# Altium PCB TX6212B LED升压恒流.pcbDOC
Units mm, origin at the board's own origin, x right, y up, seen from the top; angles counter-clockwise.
Board outline 48.79 x 35.61 mm, 2 copper layers (TopLayer, BottomLayer); 34 components, 15 nets, 80 pads, 107 vias.
Unrouted connection lines stored in the file: 1.
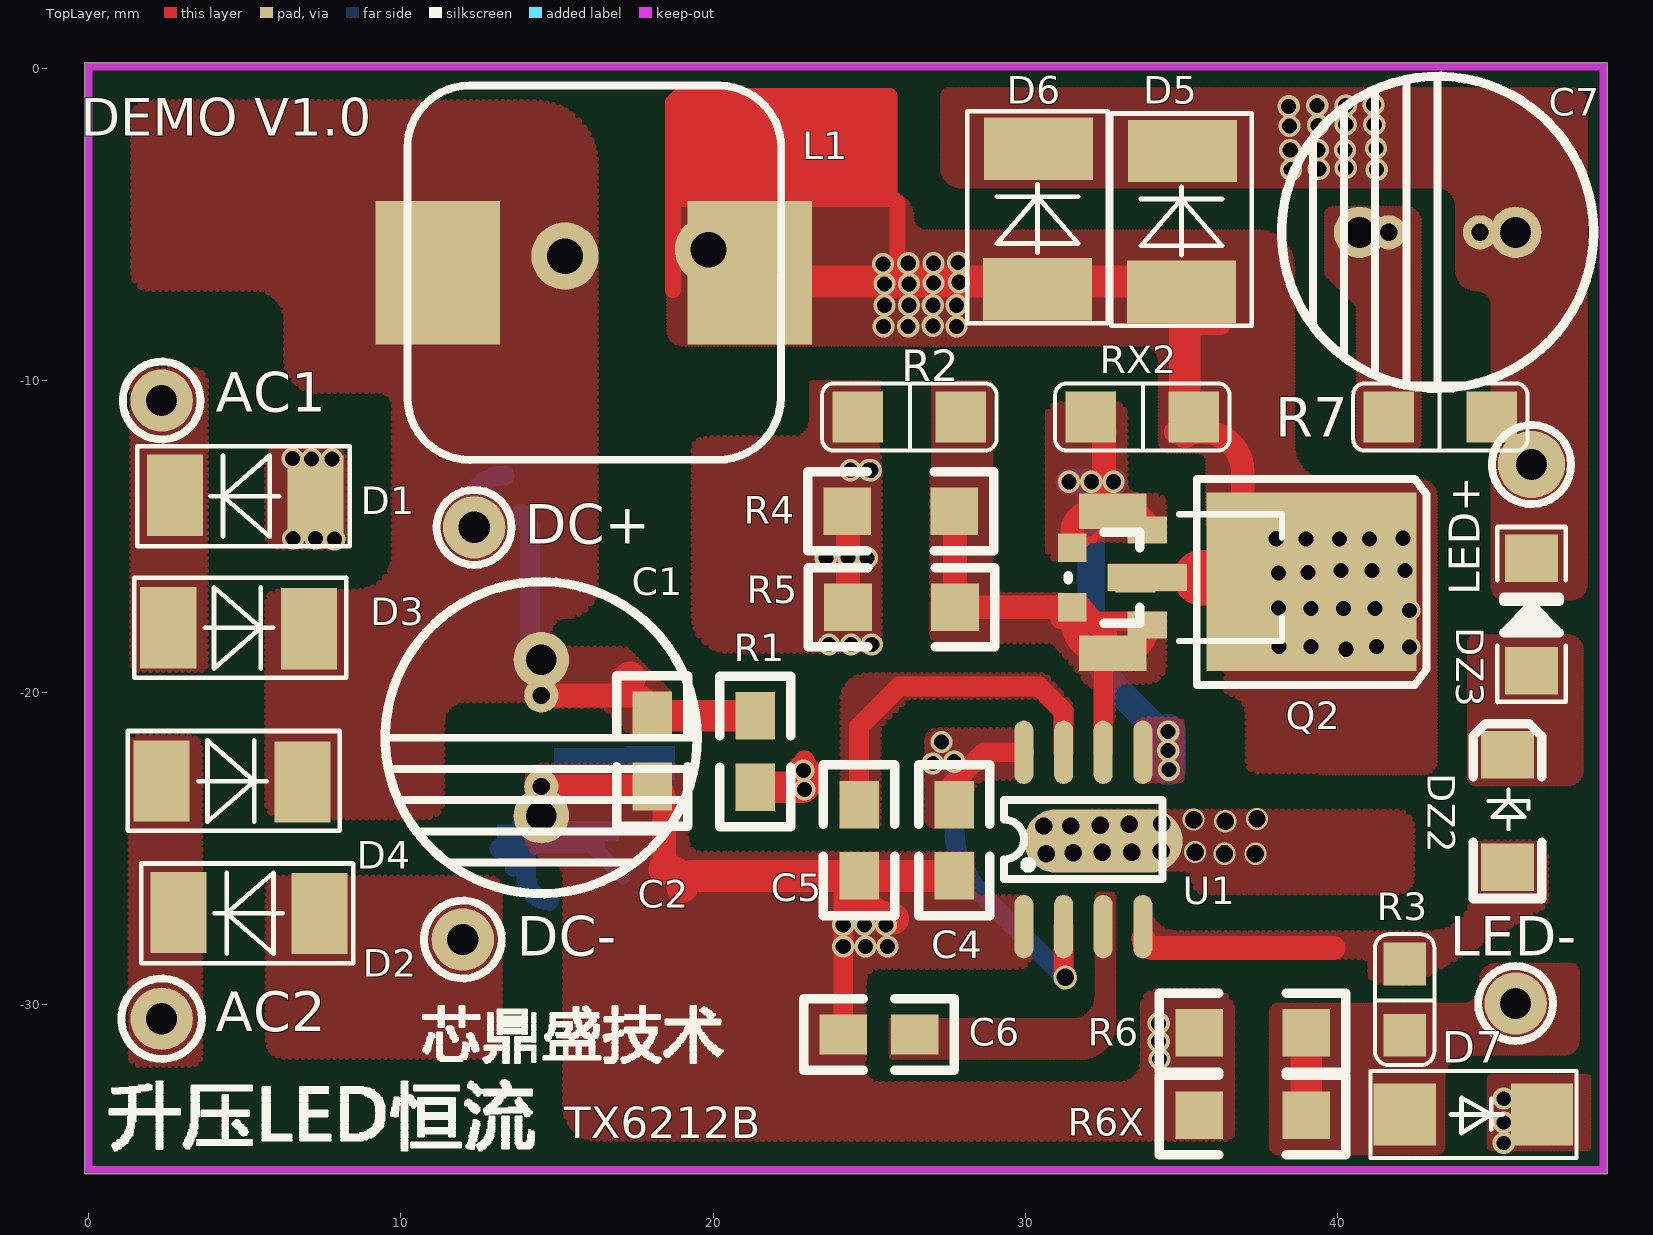
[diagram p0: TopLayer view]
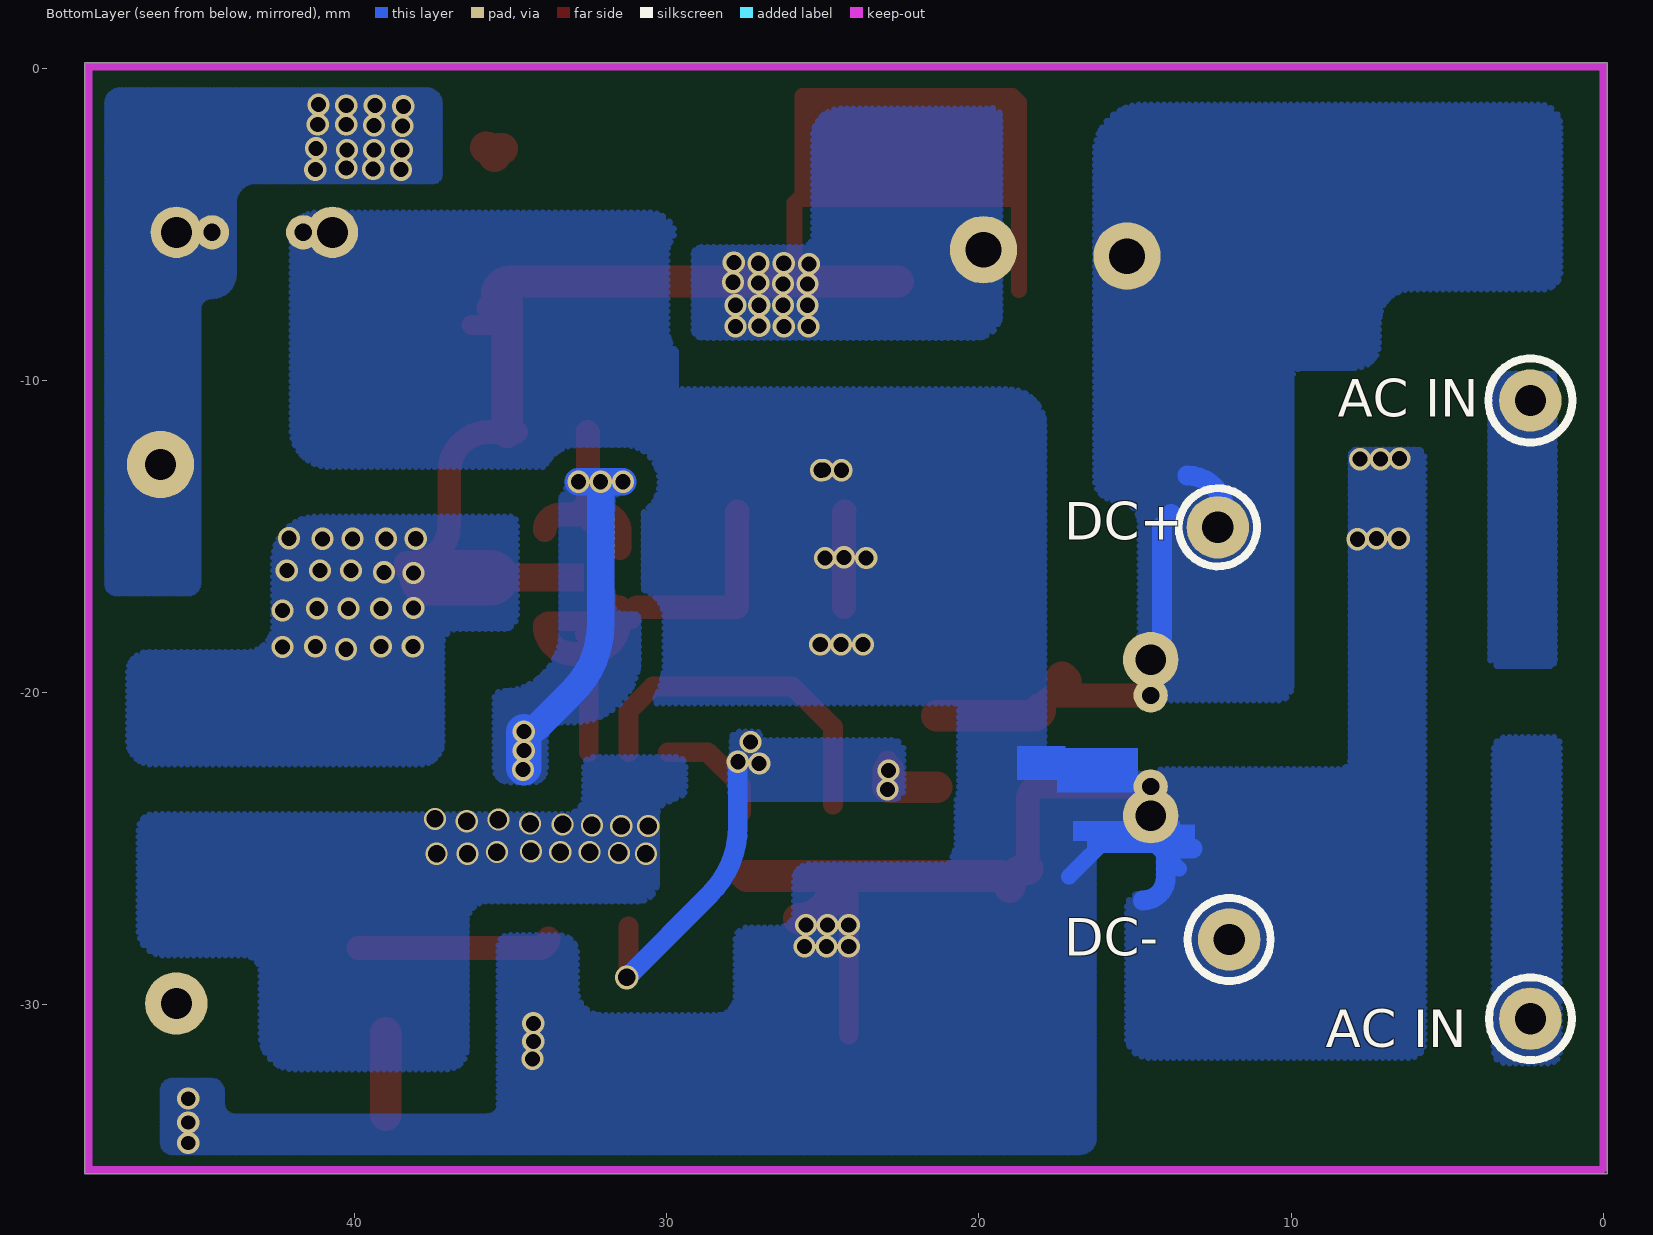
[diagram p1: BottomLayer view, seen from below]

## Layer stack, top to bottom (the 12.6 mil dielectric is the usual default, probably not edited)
TopLayer: signal copper 0.0356
Dielectric: dielectric 0.32, FR-4, Dk 4.8
BottomLayer: signal copper 0.0356

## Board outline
-0.135,-35.433 48.658,-35.433 48.658,0.178 -0.135,0.178

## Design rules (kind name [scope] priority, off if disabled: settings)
Clearance [All] p0: scope1count=1 scope1_0_kind=Board scope1_0_value=Board scope2count=1 scope2_0_kind=Board scope2_0_value=Board commentlength=0 gap=0.254
Clearance [All] p1: gap=0.254
ComponentClearance [All] p0 off: scope1count=1 scope1_0_kind=Board scope1_0_value=Board scope2count=1 scope2_0_kind=Board scope2_0_value=Board commentlength=0 gap=0.254 collisioncheckmode=3
ComponentClearance [All] p1 off: gap=0.254 collisioncheckmode=3 verticalgap=0.254 showdistances=FALSE
DiffPairsRouting [All] p0: scope1count=1 scope1_0_kind=Board scope1_0_value=Board scope2count=1 scope2_0_kind=Board scope2_0_value=Board commentlength=0
FanoutControl Fanout_BGA [All] p0 off: scope1count=1 scope1_0_kind=Board scope1_0_value=Board scope2count=1 scope2_0_kind=Board scope2_0_value=Board commentlength=69 // Protel DXP Scope 1 Expression Was: IsBGA   Fanout_BGA (Default Rule)
FanoutControl Fanout_LCC [All] p0 off: scope1count=1 scope1_0_kind=Board scope1_0_value=Board scope2count=1 scope2_0_kind=Board scope2_0_value=Board commentlength=69 // Protel DXP Scope 1 Expression Was: IsLCC   Fanout_LCC (Default Rule)
FanoutControl Fanout_SOIC [All] p0 off: scope1count=1 scope1_0_kind=Board scope1_0_value=Board scope2count=1 scope2_0_kind=Board scope2_0_value=Board commentlength=71 // Protel DXP Scope 1 Expression Was: IsSOIC   Fanout_SOIC (Default Rule)
FanoutControl Fanout_Small [All] p0 off: scope1count=1 scope1_0_kind=Board scope1_0_value=Board scope2count=1 scope2_0_kind=Board scope2_0_value=Board commentlength=84 // Protel DXP Scope 1 Expression Was: (CompPinCount < 5)   Fanout_Small (Default Rule)
FanoutControl Fanout_Default [All] p0: scope1count=1 scope1_0_kind=Board scope1_0_value=Board scope2count=1 scope2_0_kind=Board scope2_0_value=Board commentlength=30 // Fanout_Default (Default Rule)
FanoutControl Fanout_LCC [All] p1 off: bgadir=Out bgaviamode=Centered fanoutstyle=Auto fanoutdirection=Alternating viagrid=0.025 // Protel DXP Scope 1 Expression Was: IsLCC   Fanout_LCC (Default Rule)
FanoutControl Fanout_BGA [All] p2 off: bgadir=Out bgaviamode=Centered fanoutstyle=Auto fanoutdirection=Alternating viagrid=0.025 // Protel DXP Scope 1 Expression Was: IsBGA   Fanout_BGA (Default Rule)
FanoutControl Fanout_SOIC [All] p3 off: bgadir=Out bgaviamode=Centered fanoutstyle=Auto fanoutdirection=Alternating viagrid=0.025 // Protel DXP Scope 1 Expression Was: IsSOIC   Fanout_SOIC (Default Rule)
FanoutControl Fanout_Default [All] p4: bgadir=Out bgaviamode=Centered fanoutstyle=Auto fanoutdirection=Alternating viagrid=0.025 // Fanout_Default (Default Rule)
FanoutControl Fanout_Small [All] p5 off: bgadir=Out bgaviamode=Centered fanoutstyle=Auto fanoutdirection=Alternating viagrid=0.025 // Protel DXP Scope 1 Expression Was: (CompPinCount < 5)   Fanout_Small (Default Rule)
Height [All] p0: scope1count=1 scope1_0_kind=Board scope1_0_value=Board scope2count=1 scope2_0_kind=Board scope2_0_value=Board commentlength=0
HoleSize [All] p0: scope1count=1 scope1_0_kind=Board scope1_0_value=Board scope2count=1 scope2_0_kind=Board scope2_0_value=Board commentlength=0 absolutevalues=TRUE maxlimit=2.54 minlimit=0.025 maxpercent=80.000 minpercent=20.000
HoleToHoleClearance [All] p0: scope1count=1 scope1_0_kind=Board scope1_0_value=Board scope2count=1 scope2_0_kind=Board scope2_0_value=Board commentlength=0
LayerPairs [All] p0: scope1count=1 scope1_0_kind=Board scope1_0_value=Board scope2count=1 scope2_0_kind=Board scope2_0_value=Board commentlength=0 enforce=TRUE
MinimumSolderMaskSliver [All] p0: scope1count=1 scope1_0_kind=Board scope1_0_value=Board scope2count=1 scope2_0_kind=Board scope2_0_value=Board commentlength=0
NetAntennae [All] p0: scope1count=1 scope1_0_kind=Board scope1_0_value=Board scope2count=1 scope2_0_kind=Board scope2_0_value=Board commentlength=0
PasteMaskExpansion [All] p0: scope1count=1 scope1_0_kind=Board scope1_0_value=Board scope2count=1 scope2_0_kind=Board scope2_0_value=Board commentlength=0 expansion=0
PlaneClearance [All] p0: scope1count=1 scope1_0_kind=Board scope1_0_value=Board scope2count=1 scope2_0_kind=Board scope2_0_value=Board commentlength=0 clearance=0.508
PlaneConnect [All] p0: scope1count=1 scope1_0_kind=Board scope1_0_value=Board scope2count=1 scope2_0_kind=Board scope2_0_value=Board commentlength=0 planeconnectstyle=Relief reliefexpansion=0.508 reliefentries=4 reliefconductorwidth=0.254 reliefairgap=0.254
PolygonConnect [All] p0: scope1count=1 scope1_0_kind=Board scope1_0_value=Board scope2count=1 scope2_0_kind=Board scope2_0_value=Board commentlength=0 connectstyle=Direct reliefconductorwidth=0.254 reliefentries=4 polygonreliefangle="90 Angle"
PolygonConnect [All] p1: connectstyle=Direct reliefconductorwidth=0.254 reliefentries=4 polygonreliefangle="90 Angle"
RoutingCorners [All] p0: scope1count=1 scope1_0_kind=Board scope1_0_value=Board scope2count=1 scope2_0_kind=Board scope2_0_value=Board commentlength=0 cornerstyle=45-Degree minsetback=2.54 maxsetback=2.54
RoutingLayers [All] p0: scope1count=1 scope1_0_kind=Board scope1_0_value=Board scope2count=1 scope2_0_kind=Board scope2_0_value=Board commentlength=0 top layer=Horizontal bottom layer=Vertical
RoutingPriority [All] p0: scope1count=1 scope1_0_kind=Board scope1_0_value=Board scope2count=1 scope2_0_kind=Board scope2_0_value=Board commentlength=0
RoutingTopology [All] p0: scope1count=1 scope1_0_kind=Board scope1_0_value=Board scope2count=1 scope2_0_kind=Board scope2_0_value=Board commentlength=0 topology=Shortest
RoutingVias [All] p0: scope1count=1 scope1_0_kind=Board scope1_0_value=Board scope2count=1 scope2_0_kind=Board scope2_0_value=Board commentlength=0 holewidth=0.711 width=1.27 viastyle="Through Hole" minholewidth=0.711 minwidth=1.27 maxholewidth=0.711 maxwidth=1.27
RoutingVias [All] p1: holewidth=0.711 width=1.27 viastyle="Through Hole" minholewidth=0.711 minwidth=1.27 maxholewidth=0.711 maxwidth=1.27
ShortCircuit [All] p0: scope1count=1 scope1_0_kind=Board scope1_0_value=Board scope2count=1 scope2_0_kind=Board scope2_0_value=Board commentlength=0 allowed=FALSE
SilkToSilkClearance [All] p0: scope1count=1 scope1_0_kind=Board scope1_0_value=Board scope2count=1 scope2_0_kind=Board scope2_0_value=Board commentlength=0
SilkscreenOverComponentPads [All] p0: scope1count=1 scope1_0_kind=Board scope1_0_value=Board scope2count=1 scope2_0_kind=Board scope2_0_value=Board commentlength=0
SilkscreenOverComponentPads [All] p1: minsilkscreentomaskgap=0.254
SolderMaskExpansion [All] p0: scope1count=1 scope1_0_kind=Board scope1_0_value=Board scope2count=1 scope2_0_kind=Board scope2_0_value=Board commentlength=0 expansion=0.102
SolderMaskExpansion [All] p1: expansion=0.102
TestPointUsage [All] p0: scope1count=1 scope1_0_kind=Board scope1_0_value=Board scope2count=1 scope2_0_kind=Board scope2_0_value=Board commentlength=0 valid=0 allowmultiple=FALSE
TestPointUsage [All] p1: valid=0 allowmultiple=FALSE
Testpoint [All] p0: scope1count=1 scope1_0_kind=Board scope1_0_value=Board scope2count=1 scope2_0_kind=Board scope2_0_value=Board commentlength=0 side=15 testpointundercomponent=TRUE minsize=1.016 maxsize=2.54 preferedsize=1.524 minholesize=0.508 maxholesize=1.016 preferedholesize=0.813 testpointgrid=0.025 style=1023 order=0123456789
Testpoint [All] p1: side=15 testpointundercomponent=TRUE minsize=1.016 maxsize=2.54 preferedsize=1.524 minholesize=0.508 maxholesize=1.016 preferedholesize=0.813 testpointgrid=0.025 style=1023 order=0123456789
UnRoutedNet [All] p0: scope1count=1 scope1_0_kind=Board scope1_0_value=Board scope2count=1 scope2_0_kind=Board scope2_0_value=Board commentlength=0
Width [All] p0: scope1count=1 scope1_0_kind=Board scope1_0_value=Board scope2count=1 scope2_0_kind=Board scope2_0_value=Board commentlength=0 maxlimit=0.254 minlimit=0.254 preferedwidth=0.254
Width [All] p1: maxlimit=0.254 minlimit=0.254 preferedwidth=0.254
17 further rules are at their usual default settings.

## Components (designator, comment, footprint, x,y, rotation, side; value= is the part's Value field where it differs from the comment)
C1 "" CINJ#1 14.497,-18.954 r0 top
C2 "" 0805 18.053,-23.018 r90 top
C4 "" 0805 27.728,-25.883 r90 top
C5 "" 0805 24.68,-25.883 r90 top
C6 "" 0805 24.172,-30.963 r0 top
C7 "" CINJ#2 45.72,-5.258 r270 top
D1 "" SMB 7.265,-13.716 r180 top
D2 "" SMB 7.384,-27.082 r180 top
D3 "" SMB 2.54,-17.93 r0 top
D4 "" SMB 2.33,-22.84 r0 top
D5 "" SMBJ 35.011,-7.163 r90 top
D6 "" SMBJ 30.395,-7.087 r90 top
D7 "" SMA 42.164,-33.528 r180 top
DZ2 "" DZJ 146.456,79.891 r0 top
DZ3 "" DZSMA 46.228,-19.304 r0 top
L1 "" TJJ 11.176,-6.551 r0 top
Q2 "" QJJ 32.808,-14.199 r0 top
R1 "" 0805 21.353,-20.752 r270 top
R2 "" R1206 27.94,-11.176 r270 top
R3 "" R0805 42.164,-30.988 r0 top
R4 "" 1206 27.728,-14.199 r180 top
R5 "" 1206 24.325,-17.272 r0 top
R6 "" 1206 35.577,-30.912 r0 top
R6X "" 1206 35.577,-33.546 r0 top
R7 "" R1206 41.656,-11.176 r90 top
RX2 "" R1206 35.407,-11.176 r270 top
U1 "" SO8J 29.964,-27.508 r90 top
? "" DIP 15.257,-6.02 r0 top
? "LED-" OUT#1 45.72,-29.972 r0 top
? "LED+" OUT#2 46.228,-12.7 r0 top
? "DC+" OUT#1 12.345,-14.712 r0 top
? "DC-" OUT#1 11.982,-27.92 r0 top
? "AC2" OUT#1 2.33,-30.46 r0 top
? "AC1" OUT#1 2.33,-10.648 r0 top

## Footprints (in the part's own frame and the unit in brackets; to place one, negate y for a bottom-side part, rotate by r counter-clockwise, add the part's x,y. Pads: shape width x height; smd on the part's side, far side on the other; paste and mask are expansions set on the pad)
0805 [mil]
  rect 60x50 smd: 1(0,0) 2(90,0)
  silkscreen extent -50,-45 140,45
1206 [mil]
  rect 60x60 smd: 1(0,0) 2(135,0)
  silkscreen extent -50,-50 185,50
CINJ#1 [mil]
  round 70 hole 39: 1(0,0) 2(0,-196.85)
  round 43.31 hole 21.65: 1(0,-45) 2(0,-160)
  silkscreen extent -197,-295 197,98
CINJ#2 [mil]
  round 65 hole 39: 1(0,0) 2(0,-196.85)
  round 43.31 hole 21.65: 1(0,-45) 2(0,-160)
  silkscreen extent -197,-295 197,98
DIP [mil]
  round 85 hole 45: 1(0,0) 2(181,8)
DZJ [mm]
  rect 1.7x1.524 smd: 1(-100.999,-105.497) 2(-100.999,-101.897)
  silkscreen extent -102.1,-106.5 -99.9,-100.9
DZSMA [mm]
  rect 1.7x1.524 smd: 1(0,0) 2(0,3.6)
  silkscreen extent -1.1,-1.01 1.1,4.6
OUT#1 [mm]
  round 2 hole 1: 1(0,0)
OUT#2 [mm]
  round 2.159 hole 1: 1(0,0)
QJJ [mil]
  rect 36x36 smd: 1(-51.18,-46.26) 3(-51.18,-121.26)
  rect 85x45 smd: 1(0,0) 3(0,-179)
  rect 50x34 smd: 1(43.62,-23.66) 3(43.62,-143.66)
  rect 50x36 smd: 2(28.82,-84.26)
  rect 100x34 smd: 2(43.62,-83.66)
  rect 265x225 smd: 2(251,-89)
  TopLayer region: -5.91,-101.38 183.07,-101.38 183.07,-65.94 -5.91,-65.94
  TopLayer lines w10: -51.18,-46.26 -40.74,-46.26 ; -45.27,-109.25 -41.34,-109.25 ; 18.9,-185.24 28.34,-185.24
  TopLayer lines w70: 112,-83.66 192,-83.66
  silkscreen extent -56,-219 396,41
R0805 [mil]
  rect 54x54 smd: 1(0,0) 2(0,90)
  silkscreen extent -38,-38 38,128
R1206 [mil]
  rect 64x64 smd: 1(0,0) 2(0,-130)
  silkscreen extent -43,-175 43,45
SMA [mm]
  rect 2x2 smd: 1(0,0) 2(-4.4,0)
  silkscreen extent -5.5,-1.4 1.1,1.4
SMB [mm]
  rect 1.8x2.6 smd: 1(0,0) 2(4.511,-0.031)
  silkscreen extent -1.09,-1.6 5.71,1.6
SMBJ [mm]
  rect 2x3.5 smd: 1(0,0) 2(4.511,-0.031)
  silkscreen extent -1.09,-2.25 5.71,2.25
SO8J [mil]
  oval 80x200 smd: 0(108,-100.33)
  oval 80x24 smd: 1(0,0) 2(0,-50) 3(0,-100) 4(0,-150) 5(220,-150) 6(220,-100) 7(220,-50) 8(220,0)
  silkscreen extent 60,-175 160,25
TJJ [mm]
  rect 4x4.6 smd: 1(0,0) 2(10,0)
  silkscreen extent -0.97,-6 11.01,6

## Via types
v1: diameter 0.711, hole 0.483, TopLayer to BottomLayer, 87 vias
v2: diameter 0.711, hole 0.559, TopLayer to BottomLayer, 16 vias
v3: diameter 0.711, hole 0.457, TopLayer to BottomLayer, 3 vias
v4: diameter 0.762, hole 0.559, TopLayer to BottomLayer, 1 vias

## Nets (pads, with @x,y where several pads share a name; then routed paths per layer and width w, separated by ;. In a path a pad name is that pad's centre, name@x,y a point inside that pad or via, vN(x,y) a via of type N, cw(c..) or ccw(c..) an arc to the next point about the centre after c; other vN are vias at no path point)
GND: ?.1@11.982,-27.92 C1.2 C2.1 C4.1 C5.1 C6.1 C7.2 D1.1 D2.1 D7.2 R2.2 R4.2 R5.1 R6.1 R6X.1 R7.1 U1.1 | length 32
  TopLayer w0.635: C6.1 24.172,-26.441 C5.1@24.528,-26.086 ; C5.1 C4.1
  TopLayer w0.762: C1.2@14.497,-23.018 C2.1 cw(c18.053,-23.399) 18.434,-23.399 18.434,-25.66 ; R4.2 cw(c24.299,-14.224) 24.325,-14.224 R5.1
  TopLayer w1.016: 18.434,-25.66 cw(c18.434,-26.242) 19.016,-26.242 cw(c19.376,-26.242) 19.376,-25.883 C4.1@27.424,-25.883 ; C5.1 24.68,-26.162 ccw(c25.773,-26.162) v1@25.773,-27.254
  BottomLayer w0.635: 13.158,-24.999 13.854,-24.999 cw(c13.854,-25.159) 14.014,-25.159 14.014,-25.931 ccw(c14.751,-25.931) 14.751,-26.668
  other v1: 34.307,-31.75 34.282,-31.191 34.282,-30.607 24.172,-28.143 24.884,-28.143 25.595,-28.143 24.172,-27.457 24.858,-27.457 25.544,-27.457 23.715,-18.466 24.426,-18.466 25.087,-18.466 23.614,-15.697 24.934,-15.697 24.325,-15.672 7.867,-15.093 6.546,-15.068 7.258,-15.068 24.402,-12.883 24.985,-12.878 25.063,-12.883 7.131,-12.528 7.791,-12.528 6.521,-12.502
  other v3: 45.339,-34.442 45.339,-33.782 45.339,-33.02
NetA_1: ?.1@2.33,-10.648 D1.2 D3.1
NetC5_2: C5.2 U1.7 | length 11.2
  TopLayer w0.635: C5.2 24.68,-21.107 25.976,-19.812 30.446,-19.812 31.234,-20.599 U1.7
NetC6_2: C6.2 U1.3
NetD2_2: ?.1@2.33,-30.46 D2.2 D4.1
NetD3_2: ?.1@12.345,-14.712 ?.1@15.257,-6.02 C1.1 C2.2 D3.2 D4.2 L1.1 R1.1 | length 13.6
  TopLayer w0.762: C1.1@14.497,-20.097 17.418,-20.097 cw(c17.418,-20.732) C2.2
  TopLayer w1.016: 17.222,-19.634 ccw(c17.222,-19.516) 17.34,-19.516 ; C2.2@18.035,-20.523 ccw(c18.263,-20.523) 18.263,-20.752 R1.1
  BottomLayer w0.635: ?.1@12.107,-14.273 cw(c13.327,-14.273) 13.327,-13.054 ; 13.844,-14.351 13.844,-14.275 ; C1.1@14.139,-18.692 14.139,-14.679
NetD5_2: ?.1@46.228,-12.7 C7.1 D5.2 D6.2 DZ2.2 DZ3.1 DZ3.2 R7.2 | length 0.8
  TopLayer w1.016: D5.2@35.282,-2.576 cw(c35.282,-2.819) 35.526,-2.819 cw(c35.806,-2.819) D5.2@35.806,-2.54
  other v1: 38.523,-3.251 41.267,-3.251 39.412,-3.226 40.276,-3.2 38.498,-2.616 39.387,-2.616 40.251,-2.616 41.241,-2.565 38.473,-1.854 39.387,-1.829 40.276,-1.803 41.19,-1.803 38.447,-1.219 39.362,-1.194 40.276,-1.194 41.165,-1.168
NetR3_1: ?.1@45.72,-29.972 D7.1 R3.1 R6.2 R6X.2 | length 2.6
  TopLayer w1.016: R6X.2 R6.2
NetRX1_1: C4.2 R1.2 U1.2 U1.8 | length 16.6
  TopLayer w0.635: v1(22.928,-23.114) v1@22.928,-22.174 ; C4.2@27.627,-23.851 27.627,-22.987 28.694,-21.92 U1.8 ; U1.2 31.234,-29.011 ccw(c31.407,-29.011) v4(31.284,-29.134)
  TopLayer w1.016: R1.2 22.852,-23.038 ccw(c22.852,-22.962) 22.928,-22.962 cw(c22.928,-22.936) 22.902,-22.936 v1(22.902,-22.504)
  BottomLayer w0.635: v1(27.728,-22.225) 27.728,-24.308 ccw(c30.794,-24.308) 28.626,-26.476 v4(31.284,-29.134)
  other v1: 27.043,-22.276 27.322,-21.59
NetRX2_1: ?.2 D5.1 D6.1 L1.2 Q2.2 RX2.1 | length 30.8
  TopLayer w0.635: 35.069,-8.23 36.263,-8.23 ; D5.1@35.552,-7.468 cw(c35.552,-7.696) D5.1@35.78,-7.696
  TopLayer w0.762: Q2.2@33.916,-16.324 37.897,-16.324 ccw(c37.897,-15.85) 38.371,-15.85 38.193,-15.85 cw(c38.193,-14.63) 36.974,-14.63 36.974,-12.929 ccw(c35.704,-12.929) 35.704,-11.659 34.84,-11.659 ccw(c34.84,-11.557) RX2.1@34.942,-11.557
  TopLayer w1.016: L1.2@22.598,-6.833 35.044,-6.833 cw(c35.044,-7.239) 35.45,-7.239 ccw(c35.45,-7.569) 35.12,-7.569 RX2.1@35.12,-11.659
  other v1: 40.284,-18.618 38.142,-18.534 39.158,-18.534 41.267,-18.534 42.316,-18.542 42.316,-17.374 39.158,-17.315 40.2,-17.315 41.216,-17.315 38.117,-17.297 38.117,-16.18 39.064,-16.154 40.124,-16.096 41.114,-16.096 42.181,-16.096 38.048,-15.079 39.006,-15.08 40.073,-15.08 41.038,-15.08 42.112,-15.062 25.468,-8.28 26.255,-8.28 27.805,-8.28 27.043,-8.255 25.493,-7.595 26.281,-7.595 27.043,-7.595 27.805,-7.595 25.493,-6.909 26.281,-6.909 27.068,-6.883 27.881,-6.858 25.442,-6.274 26.255,-6.248 27.068,-6.248 27.855,-6.223
NetU1_3: 
NetU1_4: DZ2.1 R3.2 U1.4 | length 6.3
  TopLayer w0.762: U1.4@33.799,-27.889 ccw(c34.104,-27.889) 34.104,-28.194 39.895,-28.194
NetU1_5: Q2.1 RX2.2 U1.5 | length 19.4
  TopLayer w0.254: Q2.1@31.774,-15.374 32.05,-15.097 32.2,-15.097 32.827,-14.47 Q2.1@32.91,-14.47
  TopLayer w0.762: Q2.1@31.508,-15.374 31.508,-14.864 cw(c32.123,-14.864) 32.123,-14.249 32.758,-14.249 ccw(c32.758,-14.199) 32.808,-14.199 ccw(c32.91,-14.199) 32.91,-14.3 33.417,-14.3 cw(c33.417,-14.8) Q2.1@33.916,-14.8 ; Q2.1@32.529,-14.249 32.529,-11.684 cw(c32.554,-11.684) RX2.2@32.554,-11.659
  BottomLayer w0.889: v1(31.411,-13.251) v1(32.834,-13.251) ; v1(32.123,-13.251) 32.123,-17.805 ccw(c35.189,-17.805) 33.021,-19.973 34.109,-21.062 ccw(c34.586,-20.585) v1(34.586,-21.26) ; v1@34.586,-22.418 ccw(c34.673,-22.418) v1(34.612,-22.479)
  BottomLayer w1.143: v1@34.586,-22.418 v1(34.586,-21.26)
  other v1: 34.586,-21.869
NetU1_6: Q2.3 R2.1 R4.1 R5.2 U1.6 | length 17.2
  TopLayer w0.635: Q2.3@31.14,-17.653 31.496,-17.653 cw(c31.693,-17.653) Q2.3@31.693,-17.456 ; Q2.3@31.749,-17.729 Q2.3@33.824,-17.722 ; 31.98,-17.636 32.631,-18.128 ; Q2.3@32.453,-18.567 32.504,-18.618 U1.6
  TopLayer w0.762: R4.1 cw(c27.728,-14.224) 27.754,-14.224 R5.2 30.957,-17.272 30.957,-17.275 ccw(c30.959,-17.275) 30.959,-17.277 ; Q2.3@31.508,-17.279 31.508,-17.674 ccw(c32.605,-17.674) 32.605,-18.771 32.993,-18.771 ccw(c32.993,-17.848) Q2.3@33.916,-17.848
NewNet111: U1.0
  other v2: 30.675,-25.171 36.39,-25.171 37.38,-25.171 31.538,-25.146 32.478,-25.121 33.418,-25.121 35.45,-25.121 34.358,-25.095 30.599,-24.282 31.462,-24.282 32.402,-24.257 33.342,-24.232 34.383,-24.206 36.415,-24.13 35.399,-24.079 37.431,-24.054
copper on no net: | length 23.7
  TopLayer w0.508: 18.72,-7.112 18.72,-1.092 18.923,-0.889 25.654,-0.889 25.654,-4.064 25.908,-4.318 25.908,-6.071
  BottomLayer w0.508: 13.589,-25.652 14.788,-24.453 15.494,-24.453 ; 14.68,-24.511 15.722,-24.511 17.119,-25.908

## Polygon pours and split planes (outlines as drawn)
GND on TopLayer "TopLayer-GND" (hatched 90Degree grid 0.203 track 0.203, remove dead copper, pour order 1000): 19.778,-11.862 24.731,-11.862 cw(c24.731,-12.447) 25.316,-12.447 25.316,-18.263 cw(c24.91,-18.263) 24.91,-18.669 20.489,-18.669 cw(c20.489,-17.551) 19.372,-17.551 19.372,-12.217 cw(c19.702,-12.217) 19.702,-11.887 19.804,-11.887
NetU1_4 on TopLayer "TopLayer-NetU1_4" (hatched 90Degree grid 0.203 track 0.203, remove dead copper, pour order 1001): 33.774,-27.508 33.774,-26.873 33.977,-26.873 ccw(c34.815,-26.873) 34.815,-27.711 43.019,-27.711 ccw(c43.019,-26.365) 44.365,-26.365 44.365,-25.171 cw(c44.721,-25.171) 44.721,-24.816 46.22,-24.816 cw(c46.22,-25.298) 46.702,-25.298 46.702,-26.797 42.587,-29.21 42.435,-29.312 41.343,-29.286 cw(c41.343,-29.007) 41.063,-29.007 41.063,-28.753 ccw(c40.784,-28.753) 40.784,-28.473 34.104,-28.473 cw(c34.104,-28.169) 33.799,-28.169 33.799,-27.508
GND on TopLayer "TopLayer-GND 1" (hatched 90Degree grid 0.203 track 0.203, remove dead copper, pour order 1002): 18.153,-23.64 18.153,-27 15.257,-27 15.257,-25.984 ccw(c14.514,-25.984) 14.514,-25.241 14.514,-23.437 18.135,-23.437 18.135,-23.64
GND on TopLayer "TopLayer-GND 2" (hatched 90Degree grid 0.203 track 0.203, remove dead copper, pour order 1003): 14.063,-22.784 14.063,-24.663 ccw(c14.673,-24.663) 14.673,-25.273 15.714,-25.273 ccw(c15.714,-24.841) 16.146,-24.841 16.146,-24.409 cw(c16.527,-24.409) 16.527,-24.028 17.264,-24.028 cw(c17.264,-24.333) 17.568,-24.333 17.568,-25.933 cw(c17.086,-25.933) 17.086,-26.416 15.841,-26.416 ccw(c15.841,-27) 15.257,-27 15.257,-33.249 ccw(c16.324,-33.249) 16.324,-34.315 36.415,-34.315 ccw(c36.415,-34.087) 36.644,-34.087 36.644,-30.226 ccw(c35.983,-30.226) 35.983,-29.566 34.256,-29.566 ccw(c34.256,-30.048) 33.774,-30.048 33.774,-31.801 cw(c33.012,-31.801) 33.012,-32.563 25.341,-32.563 cw(c25.341,-32.055) 24.833,-32.055 24.833,-29.312 cw(c25.341,-29.312) 25.341,-28.804 29.735,-28.804 ccw(c29.735,-28.372) 30.167,-28.372 30.167,-26.822 ccw(c29.913,-26.822) 29.913,-26.568 28.592,-26.568 cw(c28.592,-26.289) 28.313,-26.289 28.313,-25.171 19.651,-25.171 cw(c19.651,-24.663) 19.143,-24.663 19.143,-22.784 ccw(c18.711,-22.784) 18.711,-22.352 14.495,-22.352 ccw(c14.495,-22.809) 14.038,-22.809 14.038,-22.911
NetD3_2 on TopLayer "TopLayer-NetD3_2" (hatched 90Degree grid 0.203 track 0.203, remove dead copper, pour order 1004): 7.265,-9.423 6.318,-9.423 6.318,-8.077 ccw(c5.302,-8.077) 5.302,-7.061 1.922,-7.061 cw(c1.922,-6.553) 1.414,-6.553 1.414,-1.575 cw(c1.897,-1.575) 1.897,-1.092 14.292,-1.092 cw(c14.292,-3.048) 16.248,-3.048 16.248,-16.612 cw(c15.308,-16.612) 15.308,-17.551 ccw(c15.308,-18.083) 14.776,-18.083 14.776,-18.954 11.939,-18.954 11.939,-9.423
NetU1_6 on TopLayer "TopLayer-NetU1_6" (hatched 90Degree grid 0.203 track 0.203, remove dead copper, pour order 1005): 27.017,-17.196 27.017,-18.11 ccw(c27.271,-18.11) 27.271,-18.364 30.921,-18.364 31.816,-19.449 32.115,-19.042 30.878,-17.678 27.695,-17.17 27.017,-17.17
NetRX2_1 on TopLayer "TopLayer-NetRX2_1" (hatched 90Degree grid 0.203 track 0.203, remove dead copper, pour order 1006): 36.423,-20.015 cw(c36.423,-20.719) 37.126,-20.719 37.126,-22.225 ccw(c37.431,-22.225) 37.431,-22.53 42.206,-22.53 ccw(c42.206,-22.047) 42.689,-22.047 42.689,-18.821 36.466,-18.821 36.466,-19.957
NewNet111 on TopLayer "TopLayer-NewNet111" (hatched 90Degree grid 0.203 track 0.203, remove dead copper, pour order 1007): 31.894,-24.714 31.894,-23.825 41.927,-23.825 cw(c41.927,-24.308) 42.41,-24.308 42.41,-25.883 cw(c41.876,-25.883) 41.876,-26.416 35.78,-26.416 cw(c35.78,-26.06) 35.425,-26.06 ccw(c35.018,-26.06) 35.018,-25.654 31.97,-25.654 31.97,-24.714
GND on TopLayer "TopLayer-GND 3" (hatched 90Degree grid 0.203 track 0.203, remove dead copper, pour order 1008): 34.028,-30.302 35.933,-30.302 cw(c35.933,-30.378) 36.009,-30.378 36.009,-31.75 cw(c35.755,-31.75) 35.755,-32.004 34.078,-32.004 cw(c34.078,-31.826) 33.901,-31.826 33.901,-30.505 cw(c34.078,-30.505) 34.078,-30.328 34.205,-30.328
NetD3_2 on TopLayer "TopLayer-NetD3_2 1" (hatched 90Degree grid 0.203 track 0.203, remove dead copper, pour order 1009): 14.776,-18.598 17.189,-18.598 18.586,-19.995 18.586,-21.392 17.443,-21.392 16.478,-20.427 14.497,-20.427 14.497,-18.598
NetC5_2 on TopLayer "TopLayer-NetC5_2" (hatched 90Degree grid 0.203 track 0.203, remove dead copper, pour order 1010): 24.553,-24.079 24.147,-24.079 24.147,-20.269 cw(c24.96,-20.269) 24.96,-19.456 30.649,-19.456 31.488,-20.422 31.488,-20.625 30.98,-20.701 30.472,-20.193 30.421,-20.142 26.281,-20.142 25.722,-20.701 25.493,-20.93 25.315,-21.107 25.315,-24.257 24.934,-24.257 24.934,-24.054 24.604,-24.054
NetRX1_1 on TopLayer "TopLayer-NetRX1_1" (hatched 90Degree grid 0.203 track 0.203, remove dead copper, pour order 1011): 27.932,-24.282 27.093,-24.282 cw(c27.093,-24.054) 26.865,-24.054 26.865,-21.565 cw(c27.22,-21.565) 27.22,-21.209 29.786,-21.209 29.786,-22.733 28.821,-22.733 ccw(c28.821,-23.292) 28.262,-23.292 28.262,-24.257 27.957,-24.257
NetU1_5 on TopLayer "TopLayer-NetU1_5" (hatched 90Degree grid 0.203 track 0.203, remove dead copper, pour order 1012): 33.824,-21.666 33.57,-21.666 33.57,-21.158 cw(c33.875,-21.158) 33.875,-20.853 34.866,-20.853 cw(c34.866,-21.006) 35.018,-21.006 35.018,-22.708 cw(c34.891,-22.708) 34.891,-22.835 33.748,-22.835 33.748,-22.428 33.85,-22.428 33.85,-21.692
NetU1_6 on TopLayer "TopLayer-NetU1_6 1" (hatched 90Degree grid 0.203 track 0.203, remove dead copper, pour order 1013): 27.322,-12.7 28.338,-12.7 cw(c28.338,-13.03) 28.668,-13.03 28.668,-16.256 ccw(c29.303,-16.256) 29.303,-16.891 31.758,-16.891 31.758,-17.602 31.869,-17.602 ccw(c32.351,-17.602) 32.351,-18.085 32.935,-18.085 ccw(c32.935,-17.729) 33.291,-17.729 33.291,-17.501 34.459,-17.501 34.459,-19.101 cw(c33.901,-19.101) 33.901,-19.66 33.266,-19.66 ccw(c33.266,-20.117) 32.808,-20.117 32.808,-20.93 32.504,-20.93 32.504,-19.787 32.275,-19.787 cw(c32.275,-19.329) 31.818,-19.329 ccw(c30.421,-19.329) 30.421,-17.932 27.017,-17.932 27.017,-12.979 cw(c27.271,-12.979) 27.271,-12.725 27.322,-12.725
NetU1_5 on TopLayer "TopLayer-NetU1_5 1" (hatched 90Degree grid 0.203 track 0.203, remove dead copper, pour order 1014): 31.774,-15.374 31.774,-15.723 31.03,-15.723 cw(c31.03,-15.418) 30.726,-15.418 30.726,-11.1 cw(c31.056,-11.1) 31.056,-10.77 32.859,-10.77 cw(c32.859,-11.125) 33.215,-11.125 33.215,-13.284 ccw(c33.621,-13.284) 33.621,-13.691 34.18,-13.691 cw(c34.18,-13.97) 34.459,-13.97 34.459,-15.113 32.224,-15.113 ccw(c32.224,-15.469) 31.869,-15.469 31.869,-15.57
GND on TopLayer "TopLayer-GND 4" (hatched 90Degree grid 0.203 track 0.203, remove dead copper, pour order 1015): 23.69,-12.598 24.96,-12.598 cw(c24.96,-12.979) 25.341,-12.979 25.341,-18.263 cw(c24.934,-18.263) 24.934,-18.669 23.487,-18.669 cw(c23.487,-18.44) 23.258,-18.44 23.258,-12.903 cw(c23.563,-12.903) 23.563,-12.598
GND on TopLayer "TopLayer-GND 5" (hatched 90Degree grid 0.203 track 0.203, remove dead copper, pour order 1016): 6.191,-12.172 7.74,-12.172 cw(c7.74,-12.655) 8.223,-12.655 8.223,-14.89 cw(c7.766,-14.89) 7.766,-15.347 6.115,-15.347 cw(c6.115,-14.941) 5.708,-14.941 5.708,-12.553 cw(c6.089,-12.553) 6.089,-12.172
GND on TopLayer "TopLayer-GND 6" (hatched 90Degree grid 0.203 track 0.203, remove dead copper, pour order 1017): 6.242,-25.939 12.795,-25.939 cw(c12.795,-26.32) 13.176,-26.32 13.176,-31.222 cw(c12.719,-31.222) 12.719,-31.679 6.267,-31.679 cw(c6.267,-31.146) 5.734,-31.146 5.734,-26.244 cw(c6.038,-26.244) 6.038,-25.939
NetD3_2 on TopLayer "TopLayer-NetD3_2 2" (hatched 90Degree grid 0.203 track 0.203, remove dead copper, pour order 1018): 13.564,-4.12 15.538,-4.12 15.538,-5.34 cw(c14.776,-5.34) 14.776,-6.102 ccw(c14.776,-6.61) 14.268,-6.61 cw(c14.268,-5.5) 13.158,-5.5 13.158,-4.316 13.557,-4.316
NetD3_2 on TopLayer "TopLayer-NetD3_2 3" (hatched 90Degree grid 0.203 track 0.203, remove dead copper, pour order 1019): 7.156,-4.926 13.582,-4.926 cw(c13.582,-5.611) 14.268,-5.611 14.268,-20.249 12.033,-20.249 ccw(c12.033,-20.961) 11.322,-20.961 11.322,-23.214 cw(c10.527,-23.214) 10.527,-24.009 6.191,-24.009 cw(c6.191,-23.526) 5.708,-23.526 5.708,-17.379 cw(c6.318,-17.379) 6.318,-16.77 8.891,-16.77 ccw(c8.891,-15.888) 9.772,-15.888 9.772,-10.818 ccw(c9.297,-10.818) 9.297,-10.343 7.156,-10.343 cw(c7.156,-9.843) 6.655,-9.843 6.655,-5.332 cw(c7.062,-5.332) 7.062,-4.926
NetD3_2 on TopLayer "TopLayer-NetD3_2 4" (hatched 90Degree grid 0.203 track 0.203, remove dead copper, pour order 1020): 9.772,-14.153 9.772,-10.724 ccw(c9.391,-10.724) 9.391,-10.343 7.334,-10.343 cw(c7.334,-9.327) 6.318,-9.327 6.318,-4.857 cw(c7.054,-4.857) 7.054,-4.12 13.709,-4.12 cw(c13.709,-4.679) 14.268,-4.679 14.268,-14.407 9.772,-14.407
NetD3_2 on TopLayer "TopLayer-NetD3_2 5" (hatched 90Degree grid 0.203 track 0.203, remove dead copper, pour order 1021): 6.445,-16.77 8.578,-16.77 ccw(c8.578,-15.576) 9.772,-15.576 9.772,-13.62 cw(c10.509,-13.62) 10.509,-12.883 13.963,-12.883 cw(c13.963,-13.214) 14.293,-13.214 14.293,-20.249 11.906,-20.249 ccw(c11.906,-20.834) 11.322,-20.834 11.322,-23.475 cw(c10.788,-23.475) 10.788,-24.009 6.191,-24.009 cw(c6.191,-23.526) 5.708,-23.526 5.708,-17.125 cw(c6.064,-17.125) 6.064,-16.77
NetD2_2 on TopLayer "TopLayer-NetD2_2" (hatched 90Degree grid 0.203 track 0.203, remove dead copper, pour order 1022): 2.025,-21.418 3.194,-21.418 cw(c3.194,-21.799) 3.575,-21.799 3.575,-31.629 cw(c3.27,-31.629) 3.27,-31.933 1.619,-31.933 cw(c1.619,-31.654) 1.339,-31.654 1.339,-21.646 cw(c1.568,-21.646) 1.568,-21.418
NetA_1 on TopLayer "TopLayer-NetA_1" (hatched 90Degree grid 0.203 track 0.203, remove dead copper, pour order 1023): 1.695,-9.683 3.346,-9.683 cw(c3.346,-10.089) 3.752,-10.089 3.752,-19.106 cw(c3.575,-19.106) 3.575,-19.284 1.593,-19.284 cw(c1.593,-19.081) 1.39,-19.081 1.39,-9.886 cw(c1.593,-9.886) 1.593,-9.683
GND on TopLayer "TopLayer-GND 7" (hatched 90Degree grid 0.076 track 0.076, pour order 1024): 23.114,-10.033 23.114,-11.176 cw(c22.428,-11.176) 22.428,-11.862 22.428,-13.48 25.341,-13.48 25.341,-10.033
GND on TopLayer "TopLayer-GND 8" (hatched 90Degree grid 0.076 track 0.076, remove dead copper, pour order 1025): 23.114,-11.049 23.114,-11.468 22.525,-12.057 22.525,-12.827 25.316,-12.827 25.316,-10.211 23.114,-10.211
NetU1_6 on TopLayer "TopLayer-NetU1_6 2" (hatched 90Degree grid 0.076 track 0.076, remove dead copper, pour order 1026): 27.017,-13.843
NetU1_6 on TopLayer "TopLayer-NetU1_6 3" (hatched 90Degree grid 0.076 track 0.076, remove dead copper, pour order 1027): 27.017,-13.335 27.017,-10.287 cw(c27.271,-10.287) 27.271,-10.033 28.829,-10.033 cw(c28.829,-10.16) 28.956,-10.16 28.956,-16.383 ccw(c29.464,-16.383) 29.464,-16.891 29.717,-16.891 cw(c28.683,-16.891) 28.683,-17.925 27.813,-17.925 27.813,-13.335
GND on TopLayer "TopLayer-GND 9" (hatched 90Degree grid 0.076 track 0.076, remove dead copper, pour order 1028): 44.831,-32.385 44.831,-34.544 ccw(c44.958,-34.544) 44.958,-34.671 48.006,-34.671 ccw(c48.006,-34.544) 48.133,-34.544 48.133,-32.385 ccw(c48.006,-32.385) 48.006,-32.258 44.958,-32.258 ccw(c44.958,-32.385)
NetR3_1 on TopLayer "TopLayer-NetR3_1" (hatched 90Degree grid 0.076 track 0.076, remove dead copper, pour order 1029): 47.752,-28.956 47.752,-31.115 cw(c47.244,-31.115) 47.244,-31.623 44.196,-31.623 ccw(c44.196,-32.385) 43.434,-32.385 43.434,-34.544 cw(c43.18,-34.544) 43.18,-34.798 38.1,-34.798 cw(c38.1,-34.544) 37.846,-34.544 37.846,-30.226 cw(c38.1,-30.226) 38.1,-29.972 44.069,-29.972 ccw(c44.069,-29.464) 44.577,-29.464 44.577,-29.21 cw(c45.085,-29.21) 45.085,-28.702 47.498,-28.702 cw(c47.498,-28.956)
NetD5_2 on TopLayer "TopLayer-NetD5_2" (hatched 90Degree grid 0.076 track 0.076, remove dead copper, pour order 1030): 28.321,-0.635 47.498,-0.635 cw(c47.498,-1.143) 48.006,-1.143 48.006,-16.51 cw(c47.498,-16.51) 47.498,-17.018 45.339,-17.018 cw(c45.339,-16.637) 44.958,-16.637 44.958,-7.62 ccw(c44.45,-7.62) 44.45,-7.112 cw(c44.45,-6.477) 43.815,-6.477 43.815,-4.445 ccw(c43.18,-4.445) 43.18,-3.81 27.94,-3.81 cw(c27.94,-3.175) 27.305,-3.175 27.305,-0.889 cw(c27.559,-0.889) 27.559,-0.635
NetD5_2 on TopLayer "TopLayer-NetD5_2 1" (hatched 90Degree grid 0.076 track 0.076, remove dead copper, pour order 1031): 44.196,-18.542 44.196,-22.733 ccw(c44.45,-22.733) 44.45,-22.987 47.371,-22.987 ccw(c47.371,-22.479) 47.879,-22.479 47.879,-18.669 ccw(c47.371,-18.669) 47.371,-18.161 44.45,-18.161 ccw(c44.45,-18.415) 44.196,-18.415
NetC6_2 on TopLayer "TopLayer-NetC6_2" (hatched 90Degree grid 0.076 track 0.076, remove dead copper, pour order 1032): 32.258,-26.543 32.258,-29.718 cw(c31.496,-29.718) 31.496,-30.48 25.654,-30.48 25.654,-31.623 ccw(c25.781,-31.623) 25.781,-31.75 31.75,-31.75 ccw(c31.75,-30.607) 32.893,-30.607 32.893,-26.543 ccw(c32.766,-26.543) 32.766,-26.416 32.385,-26.416 ccw(c32.385,-26.543)
GND on TopLayer "TopLayer-GND 10" (hatched 90Degree grid 0.102 track 0.102, remove dead copper, pour order 1033): 39.497,-4.572
GND on TopLayer "TopLayer-GND 11" (hatched 90Degree grid 0.102 track 0.102, remove dead copper, pour order 1034): 39.624,-4.826 39.624,-6.604 40.64,-7.62 40.64,-11.938 ccw(c40.894,-11.938) 40.894,-12.192 42.418,-12.192 ccw(c42.418,-11.938) 42.672,-11.938 42.672,-4.953 ccw(c42.164,-4.953) 42.164,-4.445 39.878,-4.445 ccw(c39.878,-4.699) 39.624,-4.699
NetRX2_1 on TopLayer "TopLayer-NetRX2_1 1" (hatched 90Degree grid 0.102 track 0.102, remove dead copper, pour order 1035): 18.669,-3.937 25.527,-3.937 cw(c25.527,-4.826) 26.416,-4.826 ccw(c26.797,-4.826) 26.797,-5.207 37.465,-5.207 cw(c37.465,-6.35) 38.608,-6.35 38.608,-12.065 ccw(c39.751,-12.065) 39.751,-13.208 42.672,-13.208 cw(c42.672,-13.716) 43.18,-13.716 43.18,-22.225 cw(c42.799,-22.225) 42.799,-22.606 39.37,-22.606 39.37,-14.605 35.814,-14.605 35.814,-12.573 ccw(c35.56,-12.573) 35.56,-12.319 34.671,-12.319 cw(c34.671,-11.938) 34.29,-11.938 34.29,-9.398 ccw(c33.782,-9.398) 33.782,-8.89 19.05,-8.89 cw(c19.05,-8.382) 18.542,-8.382 18.542,-4.064 cw(c18.669,-4.064) 18.669,-3.937
NewNet111 on BottomLayer "BottomLayer-NewNet111" (hatched 90Degree grid 0.076 track 0.076, remove dead copper, pour order 1036): 29.337,-24.257
NewNet111 on BottomLayer "BottomLayer-NewNet111 1" (hatched 90Degree grid 0.203 track 0.203, remove dead copper, pour order 1037): 30.319,-22.073 32.351,-22.073 cw(c32.351,-22.377) 32.656,-22.377 32.656,-23.317 ccw(c33.24,-23.317) 33.24,-23.901 46.423,-23.901 cw(c46.423,-24.409) 46.931,-24.409 46.931,-27.61 cw(c46.118,-27.61) 46.118,-28.423 43.578,-28.423 ccw(c43.578,-28.981) 43.019,-28.981 43.019,-30.988 cw(c41.927,-30.988) 41.927,-32.08 37.076,-32.08 cw(c37.076,-31.42) 36.415,-31.42 36.415,-27.381 ccw(c35.729,-27.381) 35.729,-26.695 30.929,-26.695 cw(c30.929,-26.086) 30.319,-26.086 30.319,-23.952 ccw(c29.862,-23.952) 29.862,-23.495 ccw(c29.76,-23.495) 29.76,-23.393 cw(c29.76,-23.038) 29.405,-23.038 29.405,-22.377 cw(c29.71,-22.377) 29.71,-22.073
GND on BottomLayer "BottomLayer-GND" (hatched 90Degree grid 0.203 track 0.203, remove dead copper, pour order 1038): 16.654,-21.971 17.899,-21.971 17.899,-11.455 cw(c19.067,-11.455) 19.067,-10.287 29.71,-10.287 29.71,-5.486 cw(c30.573,-5.486) 30.573,-4.623 41.216,-4.623 cw(c41.216,-5.436) 42.029,-5.436 42.029,-11.557 cw(c40.809,-11.557) 40.809,-12.776 30.751,-12.776 30.751,-20.345 20.642,-20.345 20.642,-24.333 16.712,-24.333 16.712,-21.996
GND on BottomLayer "BottomLayer-GND 1" (hatched 90Degree grid 0.203 track 0.203, remove dead copper, pour order 1039): 14.851,-22.624 19.778,-22.624 cw(c19.778,-23.564) 20.718,-23.564 20.718,-25.123 ccw(c21.097,-25.123) 21.097,-25.502 25.392,-25.502 cw(c25.392,-26.035) 25.925,-26.035 25.925,-27.051 ccw(c26.408,-27.051) 26.408,-27.534 27.398,-27.534 cw(c27.398,-27.94) 27.805,-27.94 27.805,-29.743 ccw(c28.414,-29.743) 28.414,-30.353 32.046,-30.353 ccw(c32.046,-29.515) 32.885,-29.515 32.885,-28.346 cw(c33.443,-28.346) 33.443,-27.788 35.069,-27.788 cw(c35.069,-28.118) 35.399,-28.118 35.399,-33.63 cw(c34.688,-33.63) 34.688,-34.341 18.051,-34.341 cw(c18.051,-32.715) 16.425,-32.715 16.425,-25.375 ccw(c15.562,-25.375) 15.562,-24.511 14.571,-24.511 14.571,-22.827 14.876,-22.827 14.876,-22.624
GND on BottomLayer "BottomLayer-GND 2" (hatched 90Degree grid 0.203 track 0.203, remove dead copper, pour order 1040): 13.962,-22.604 19.55,-22.604 cw(c19.55,-23.772) 20.718,-23.772 20.718,-24.816 ccw(c21.556,-24.816) 21.556,-25.654
NetRX2_1 on BottomLayer "BottomLayer-NetRX2_1" (hatched 90Degree grid 0.203 track 0.203, remove dead copper, pour order 1041): 19.753,-1.295 24.401,-1.295 cw(c24.401,-2.21) 25.315,-2.21 25.315,-5.359 ccw(c25.696,-5.359) 25.696,-5.74 28.897,-5.74 cw(c28.897,-5.994) 29.151,-5.994 29.151,-8.331 cw(c28.846,-8.331) 28.846,-8.636 20.083,-8.636 cw(c20.083,-7.874) 19.321,-7.874 19.321,-1.549 cw(c19.6,-1.549) 19.6,-1.27 19.753,-1.27
NetD3_2 on BottomLayer "BottomLayer-NetD3_2" (hatched 90Degree grid 0.203 track 0.203, remove dead copper, pour order 1042): 8.831,-9.599 7.341,-8.11 7.181,-8.11 ccw(c6.158,-8.11) 6.158,-7.087 1.947,-7.087 cw(c1.947,-6.502) 1.363,-6.502 1.363,-1.854 cw(c2.049,-1.854) 2.049,-1.168 14.749,-1.168 cw(c14.749,-2.701) 16.282,-2.701 16.282,-13.157 cw(c15.571,-13.157) 15.571,-13.868 ccw(c15.571,-14.589) 14.851,-14.589 14.851,-18.593 13.844,-18.593 13.844,-9.599
NetRX2_1 on BottomLayer "BottomLayer-NetRX2_1 1" (hatched 90Degree grid 0.203 track 0.203, remove dead copper, pour order 1043): 35.298,-14.376 41.241,-14.376 cw(c41.241,-15.748) 42.613,-15.748 42.613,-17.805 ccw(c43.527,-17.805) 43.527,-18.72 46.651,-18.72 cw(c46.651,-19.329) 47.261,-19.329 47.261,-21.565 cw(c46.524,-21.565) 46.524,-22.301 37.888,-22.301 cw(c37.888,-21.615) 37.203,-21.615 37.203,-18.491 ccw(c36.669,-18.491) 36.669,-17.958 35.221,-17.958 cw(c35.221,-17.551) 34.815,-17.551 34.815,-14.58 cw(c35.018,-14.58) 35.018,-14.376
NetRX1_1 on BottomLayer "BottomLayer-NetRX1_1" (hatched 90Degree grid 0.203 track 0.203, remove dead copper, pour order 1044): 22.42,-22.454 22.42,-21.869 cw(c22.75,-21.869) 22.75,-21.539 26.865,-21.539 ccw(c26.865,-21.387) 27.017,-21.387 cw(c27.144,-21.387) 27.144,-21.26 27.678,-21.26 cw(c27.678,-21.514) 27.932,-21.514 27.932,-22.395 22.725,-22.395 ccw(c22.834,-22.395) 22.834,-22.504 22.42,-22.504
GND on BottomLayer "BottomLayer-GND 3" (hatched 90Degree grid 0.203 track 0.203, remove dead copper, pour order 1045): 7.131,-19.556 8.096,-19.556 8.096,-22.129 ccw(c8.426,-22.129) 8.426,-22.459 14.116,-22.459 cw(c14.116,-22.586) 14.243,-22.586 14.243,-25.863 cw(c13.64,-25.863) 13.64,-26.465 8.078,-26.465 8.078,-23.214 7.062,-23.214 7.062,-19.556
NetRX1_1 on BottomLayer "BottomLayer-NetRX1_1 1" (hatched 90Degree grid 0.203 track 0.203, remove dead copper, pour order 1046): 22.775,-22.022 27.805,-22.022 cw(c27.805,-22.2) 27.982,-22.2 27.982,-23.114 cw(c27.678,-23.114) 27.678,-23.419 22.75,-23.419 cw(c22.75,-23.089) 22.42,-23.089 22.42,-22.25 cw(c22.648,-22.25) 22.648,-22.022
GND on BottomLayer "BottomLayer-GND 4" (hatched 90Degree grid 0.203 track 0.203, remove dead copper, pour order 1047): 6.572,-12.223 7.893,-12.223 cw(c7.893,-12.426) 8.096,-12.426 8.096,-25.888 ccw(c8.655,-25.888) 8.655,-26.447 14.801,-26.447 cw(c14.801,-26.904) 15.259,-26.904 15.259,-31.019 cw(c14.573,-31.019) 14.573,-31.705 6.191,-31.705 cw(c6.191,-31.248) 5.734,-31.248 5.734,-12.452 cw(c5.962,-12.452) 5.962,-12.223
NetD3_2 on BottomLayer "BottomLayer-NetD3_2 1" (hatched 90Degree grid 0.203 track 0.203, remove dead copper, pour order 1048): 8.045,-2.487 15.589,-2.487 cw(c15.589,-3.181) 16.282,-3.181 16.282,-9.193 cw(c15.469,-9.193) 15.469,-10.006 ccw(c15.469,-11.055) 14.42,-11.055 14.42,-20.249 10.407,-20.249 cw(c10.407,-19.825) 9.983,-19.825 9.983,-9.962 ccw(c9.62,-9.962) 9.62,-9.599 7.951,-9.599 cw(c7.951,-8.83) 7.181,-8.83 7.181,-2.894 cw(c7.588,-2.894) 7.588,-2.487
NetD2_2 on BottomLayer "BottomLayer-NetD2_2" (hatched 90Degree grid 0.203 track 0.203, remove dead copper, pour order 1049): 1.898,-21.443 3.092,-21.443 cw(c3.092,-21.85) 3.498,-21.85 3.498,-31.502 cw(c3.117,-31.502) 3.117,-31.883 1.746,-31.883 cw(c1.746,-31.527) 1.39,-31.527 1.39,-21.646 cw(c1.593,-21.646) 1.593,-21.443
NetA_1 on BottomLayer "BottomLayer-NetA_1" (hatched 90Degree grid 0.203 track 0.203, remove dead copper, pour order 1050): 1.771,-9.785 3.194,-9.785 cw(c3.194,-10.216) 3.625,-10.216 3.625,-18.878 cw(c3.346,-18.878) 3.346,-19.157 1.746,-19.157 cw(c1.746,-18.954) 1.543,-18.954 1.543,-9.886 cw(c1.644,-9.886) 1.644,-9.785
NetU1_5 on BottomLayer "BottomLayer-NetU1_5" (hatched 90Degree grid 0.203 track 0.203, remove dead copper, pour order 1051): 32.402,-13.251 32.402,-12.903 33.164,-12.903 cw(c33.164,-13.132) 33.393,-13.132 33.393,-18.059 ccw(c35.298,-18.059) 35.298,-19.964 cw(c35.298,-20.193) 35.526,-20.193 35.526,-22.403 cw(c35.044,-22.403) 35.044,-22.885 34.332,-22.885 cw(c34.332,-22.428) 33.875,-22.428 33.875,-21.488 ccw(c33.342,-21.488) 33.342,-20.955 32.961,-20.955 cw(c32.961,-18.898) 30.903,-18.898 30.903,-17.653 cw(c31.056,-17.653) 31.056,-17.501 31.386,-17.501 ccw(c31.386,-17.145) 31.742,-17.145 31.742,-13.97 ccw(c31.31,-13.97) 31.31,-13.538 31.31,-12.954 31.919,-12.954 31.919,-13.251
GND on BottomLayer "BottomLayer-GND 5" (hatched 90Degree grid 0.076 track 0.076, remove dead copper, pour order 1052): 35.399,-31.565 35.399,-33.147 ccw(c35.78,-33.147) 35.78,-33.528 43.815,-33.528 ccw(c43.815,-33.147) 44.196,-33.147 44.196,-32.766 cw(c44.577,-32.766) 44.577,-32.385 45.847,-32.385 cw(c45.847,-32.766) 46.228,-32.766 46.228,-34.417 cw(c45.847,-34.417) 45.847,-34.798 16.764,-34.798 cw(c16.764,-34.29) 16.256,-34.29 16.256,-24.511 18.338,-24.511 18.338,-28.702 ccw(c21.513,-28.702) 21.513,-31.877 35.399,-31.877
NetD5_2 on BottomLayer "BottomLayer-NetD5_2" (hatched 90Degree grid 0.076 track 0.076, remove dead copper, pour order 1053): 37.719,-3.683 43.18,-3.683 cw(c43.18,-4.318) 43.815,-4.318 43.815,-6.604 ccw(c44.577,-6.604) 44.577,-7.366 cw(c44.577,-7.747) 44.958,-7.747 44.958,-16.51 ccw(c45.339,-16.51) 45.339,-16.891 47.625,-16.891 ccw(c47.625,-16.51) 48.006,-16.51 48.006,-1.143 ccw(c47.498,-1.143) 47.498,-0.635 37.719,-0.635 ccw(c37.719,-1.143) 37.211,-1.143 37.211,-3.429 ccw(c37.465,-3.429) 37.465,-3.683
NewNet111 on BottomSolder (hatched 90Degree grid 0.076 track 0.076, remove dead copper): 29.591,-24.003 29.591,-25.527 30.734,-26.67 30.988,-26.924 39.751,-26.924 ccw(c39.751,-26.416) 40.259,-26.416 40.259,-23.749 ccw(c40.005,-23.749) 40.005,-23.495 29.972,-23.495 ccw(c29.972,-23.876) 29.591,-23.876

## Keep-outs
KeepOutLayer:
  lines w0.254: -0.008,0.051 -0.008,-35.255 0.042,-35.306 48.531,-35.306 48.531,0.051 0.017,0.051

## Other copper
TopLayer:
  region net NetU1_6: 32.361,-17.901 32.614,-17.689 31.945,-16.891 31.692,-17.103
  rectangle net NetRX2_1: 18.72,-4.445 25.73,-1.092
BottomLayer:
  rectangle net GND: 17.222,-22.807 18.789,-21.723
  rectangle net GND: 14.903,-23.214 17.494,-21.791
  rectangle net GND: 13.564,-24.765 16.993,-24.13
  rectangle net GND: 13.081,-25.146 16.535,-24.23

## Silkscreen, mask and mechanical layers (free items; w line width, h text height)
TopOverlay:
  drawing of 1566 lines, arcs and shapes, not listed
  text "DEMO V1.0" at -0.254,-2.159 h1.2
  text "TX6212B" at 15.24,-34.29 h1.02
BottomOverlay:
  circle w0.254: c2.33,-30.46 r1.331
  circle w0.254: c2.33,-10.648 r1.349
  circle w0.254: c12.345,-14.712 r1.253
  circle w0.254: c11.982,-27.92 r1.331
  text "AC IN" at 8.509,-11.176 h1.2
  text "DC+" at 17.272,-15.113 h1.2
  text "DC-" at 17.272,-28.448 h1.2
  text "AC IN" at 8.89,-31.369 h1.2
